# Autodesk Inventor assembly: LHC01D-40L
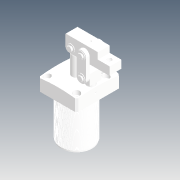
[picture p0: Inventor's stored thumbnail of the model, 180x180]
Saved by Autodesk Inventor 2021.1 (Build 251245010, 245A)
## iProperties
Created: 2019-04
Part Number: LHC01D-40L
Description: STEP AP214
Document SubType Name: Assembly
Designer: user
Title: LHC01D-40L.STEP
Revision Number: ÈÎºÎ
Sending System: SolidWorks 2016
Preprocessor: SwSTEP 2.0
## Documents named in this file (12)
- D:\Vault_2016\Projekty\Clamptek\Hydraulic\LHC01D\Inventor\LHC01D-40L\LHC01D-40L.iam
- D:\Vault_2016\Projekty\Clamptek\Hydraulic\LHC01D\Inventor\LHC01D-40L\LHC01D40»îÈû¸Ë.ipt
- D:\Vault_2016\Projekty\Clamptek\Hydraulic\LHC01D\Inventor\LHC01D-40L\CPLCU-40ZCK.ipt
- D:\Vault_2016\Projekty\Clamptek\Hydraulic\LHC01D\Inventor\LHC01D-40L\CPLCU-40YB.ipt
- D:\Vault_2016\Projekty\Clamptek\Hydraulic\LHC01D\Inventor\LHC01D-40L\CPLCU-40LG.ipt
- D:\Vault_2016\Projekty\Clamptek\Hydraulic\LHC01D\Inventor\LHC01D-40L\CPLCU-40DX.ipt
- D:\Vault_2016\Projekty\Clamptek\Hydraulic\LHC01D\Inventor\LHC01D-40L\CPLCU-40X.ipt
- D:\Vault_2016\Projekty\Clamptek\Hydraulic\LHC01D\Inventor\LHC01D-40L\LHC01D-40-05.ipt
- D:\Vault_2016\Projekty\Clamptek\Hydraulic\LHC01D\Inventor\LHC01D-40L\LHC01D-40-08.ipt
- D:\Vault_2016\Projekty\Clamptek\Hydraulic\LHC01D\Inventor\LHC01D-40L\M4ningjin_4.ipt
- D:\Vault_2016\Projekty\Clamptek\Hydraulic\LHC01D\Inventor\LHC01D-40L\¶ÂÍ·_7.ipt
- D:\Vault_2016\Projekty\Clamptek\Hydraulic\LHC01D\Inventor\LHC01D-40L\040L±¾Ìå.ipt
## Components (24 placed, 24 different names)
1. LHC01D40»îÈû¸Ë_1
2. CPLCU-40ZCK_2
3. CPLCU-40YB_3
4. CPLCU-40LG_4
5. CPLCU-40LG_5
6. CPLCU-40DX_6
7. CPLCU-40X_7
8. CPLCU-40X_8
9. LHC01D-40-05_9
10. LHC01D-40-05_10
11. LHC01D-40-05_11
12. LHC01D-40-05_12
13. LHC01D-40-05_13
14. LHC01D-40-05_14
15. LHC01D-40-08_15
16. LHC01D-40-08_16
17. LHC01D-40-08_17
18. LHC01D-40-08_18
19. LHC01D-40-08_19
20. LHC01D-40-08_20
21. M4ningjin_4_21
22. ¶ÂÍ·_7_22
23. ¶ÂÍ·_7_23
24. 040L±¾Ìå_24
